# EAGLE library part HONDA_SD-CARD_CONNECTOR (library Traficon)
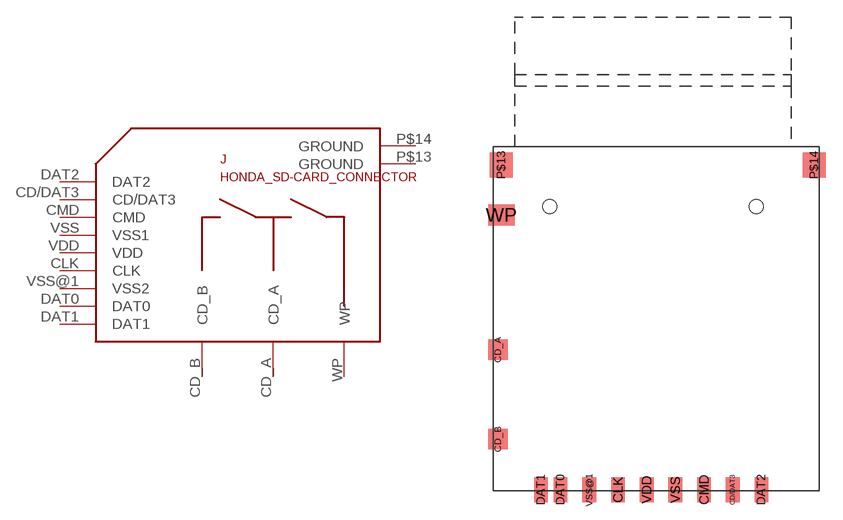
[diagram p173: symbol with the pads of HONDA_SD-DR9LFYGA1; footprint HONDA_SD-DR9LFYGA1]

Designator prefix J

## HONDA_SD-CARD_CONNECTOR  [HONDA_SD-DR9LFYGA1]
CD/DAT3  CD/DAT3
CD_A  CD_A
CD_B  CD_B
CLK  CLK
CMD  CMD
DAT0  DAT0
DAT1  DAT1
DAT2  DAT2
P$13  GROUND
P$14  GROUND
VDD  VDD
VSS  VSS1
VSS@1  VSS2
WP  WP

## Footprint HONDA_SD-DR9LFYGA1 (pad centres in mm)
smd 1.2 x 2.2: CD/DAT3 6.95,-29.9; CLK -3.05,-29.9; CMD 4.45,-29.9; DAT0 -8.05,-29.9; DAT1 -9.75,-29.9; DAT2 9.45,-29.9; VDD -0.55,-29.9; VSS 1.95,-29.9; VSS@1 -5.55,-29.9
smd 1.7 x 1.8: CD_A -13.5,-17.7; CD_B -13.5,-25.5
smd 2 x 2.2: P$13 -13.2,-1.6; P$14 14.05,-1.6
smd 2.3 x 1.8: WP -13.2,-5.95
hole 1.2 at -9,-5.2
hole 1.2 at 9,-5.2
